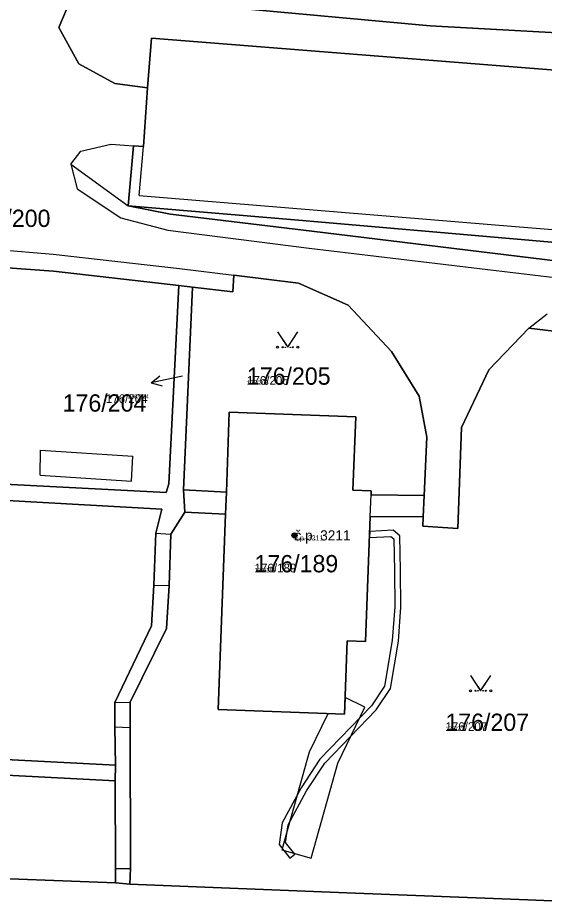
# Model space of a CAD drawing. Extents: x -759873 to -758487, y -975024 to -973516.
# Drawn here: x -759623.1 to -759571.4, y -974856.7 to -974770.4 of the extents above; entities that cross this region are included whole.
import ezdxf

# ---------------------------------------------------------------- set-up
doc = ezdxf.new("R2010")
doc.units = 0
for name, color, linetype in [('KAT_02_hranice parcel', 7, 'Continuous'), ('KAT_03_1000_st čísla parcelní', 7, 'Continuous'), ('KAT_03_1000_čísla parcelní', 7, 'Continuous'), ('KAT_03_1000_čísla popisná', 7, 'Continuous'), ('KAT_03_250_st čísla parcelní', 7, 'Continuous'), ('KAT_03_250_čísla parcelní', 7, 'Continuous'), ('KAT_03_250_čísla popisná', 7, 'Continuous'), ('KAT_03_500_st čísla parcelní', 7, 'Continuous'), ('KAT_03_500_čísla parcelní', 7, 'Continuous'), ('KAT_03_500_čísla popisná', 7, 'Continuous'), ('KAT_04_vnitřní kresba', 7, 'Continuous'), ('KAT_05_1000_značky kultur', 7, 'Continuous'), ('KAT_05_250_značky kultur', 7, 'Continuous'), ('KAT_05_500_značky kultur', 7, 'Continuous'), ('KAT_07_1000_značky budov', 7, 'Continuous'), ('KAT_07_250_značky budov', 7, 'Continuous'), ('KAT_07_500_značky budov', 7, 'Continuous'), ('KAT_10_věcná břemena', 7, 'Continuous'), ('KAT_12_pomocná šipka', 7, 'Continuous'), ('KAT_14_plocha_budovy', 7, 'Continuous'), ('KAT_14_plocha_pozemek', 7, 'Continuous')]:
    doc.layers.add(name, color=color, linetype=linetype)

msp = doc.modelspace()

# ---------------------------------------------------------------- linework, layer by layer
at = {"layer": 'KAT_02_hranice parcel'}
for p, q in [((-759607.29, -974796.68), (-759605.95, -974796.84)), ((-759606.81, -974816.78), (-759605.95, -974796.84)), ((-759606.81, -974816.78), (-759606.69, -974818.97)), ((-759583.29, -974819.43), (-759583.18, -974817.31)), ((-759613.54, -974845.35), (-759613.5, -974843.8)), ((-759612.08, -974855.52), (-759613.51, -974855.38))]:
    msp.add_line(p, q, dxfattribs=at)
for points in [[(-759493.33, -974775.87), (-759498.32, -974775.83), (-759582.59, -974771.17), (-759622.27, -974767.52)], [(-759610.35, -974777.27), (-759613.56, -974776.84), (-759617.11, -974774.92), (-759619.06, -974771.36), (-759617.87, -974768.52), (-759622.27, -974767.52)], [(-759500.61, -974785.93), (-759500.3, -974781.07), (-759541.75, -974777.79), (-759572.8, -974775.33), (-759609.95, -974772.38), (-759610.35, -974777.27)], [(-759612.26, -974788.87), (-759611.74, -974782.97), (-759610.74, -974783.04), (-759610.35, -974777.27)], [(-759506.34, -974821.05), (-759506.33, -974817.78), (-759508.64, -974810.72), (-759514.71, -974803.91), (-759522.15, -974800.74), (-759530.11, -974799.18), (-759550.41, -974796.65), (-759570.02, -974794.3), (-759594.2, -974791.34), (-759608.08, -974789.67), (-759612.26, -974788.87)], [(-759612.26, -974788.87), (-759595.53, -974790.27), (-759574.41, -974792.12), (-759557.24, -974793.62), (-759539.2, -974795.18), (-759522.98, -974796.45), (-759500.22, -974797.96), (-759499.79, -974792.57), (-759501.06, -974792.24)], [(-759658.47, -974814.76), (-759658.14, -974807.03), (-759656.32, -974802.8), (-759652.94, -974797.71), (-759651.6, -974796.18), (-759650.1, -974795.21), (-759637.14, -974794.79), (-759628.18, -974794.67), (-759619.59, -974795.29), (-759607.29, -974796.68)], [(-759605.95, -974796.84), (-759601.97, -974797.3), (-759601.86, -974795.66), (-759595.52, -974796.45), (-759590.65, -974798.61), (-759586.4, -974803.18), (-759583.69, -974807.58), (-759582.91, -974811.58), (-759583.18, -974817.31)], [(-759635.19, -974815.65), (-759608.52, -974817.04), (-759608.26, -974816.17), (-759607.29, -974796.68)], [(-759583.29, -974819.43), (-759583.32, -974820.34), (-759579.88, -974820.55), (-759579.53, -974810.64), (-759576.85, -974804.99), (-759572.9, -974800.89), (-759557.33, -974802.75)], [(-759583.18, -974817.31), (-759588.4, -974817.27), (-759588.39, -974816.87), (-759590.2, -974816.8), (-759589.9, -974809.61), (-759602.32, -974809.12), (-759602.61, -974817), (-759606.81, -974816.78)], [(-759613.5, -974843.8), (-759613.55, -974840.04), (-759613.55, -974837.66), (-759609.96, -974830.14), (-759609.73, -974826.13), (-759609.54, -974821.02), (-759608.96, -974818.66), (-759635.26, -974817.18)], [(-759613.54, -974845.35), (-759644.32, -974843.75), (-759652.64, -974841.53), (-759658.71, -974839.08), (-759660.02, -974837.93), (-759660.42, -974836.39), (-759660.21, -974820.73), (-759660.31, -974819.06)], [(-759658.82, -974818.97), (-759658.71, -974820.63), (-759658.89, -974836.21), (-759657.92, -974837.78), (-759652.31, -974840.06), (-759644, -974842.25), (-759613.5, -974843.8)], [(-759612.08, -974855.52), (-759612.01, -974853.96), (-759612.06, -974840.11), (-759612.04, -974837.62), (-759608.5, -974830.39), (-759608.23, -974826.18), (-759608.06, -974821.13), (-759606.69, -974818.97)], [(-759606.69, -974818.97), (-759602.69, -974819.15), (-759603.4, -974838.36), (-759591.01, -974838.82), (-759590.75, -974831.6), (-759588.94, -974831.66), (-759588.48, -974819.39), (-759583.29, -974819.43)], [(-759613.51, -974855.38), (-759613.51, -974853.96), (-759613.54, -974845.35)], [(-759613.51, -974855.38), (-759629.09, -974854.78), (-759656.08, -974853.68), (-759679.76, -974852.8), (-759694.68, -974852.23), (-759697.34, -974852.13), (-759701.47, -974851.98), (-759711.23, -974851.62), (-759720.36, -974851.23)], [(-759558.86, -974857.64), (-759572.99, -974857.06), (-759590.79, -974856.36), (-759612.08, -974855.52)]]:
    msp.add_lwpolyline(points, dxfattribs=at)
at = {"layer": 'KAT_03_1000_čísla popisná'}
msp.add_circle((-759595.92, -974821.24), 0.25, dxfattribs=at)
at = {"layer": 'KAT_03_250_čísla popisná'}
msp.add_circle((-759595.92, -974821.24), 0.0625, dxfattribs=at)
at = {"layer": 'KAT_03_500_čísla popisná'}
msp.add_circle((-759595.92, -974821.24), 0.125, dxfattribs=at)
at = {"layer": 'KAT_04_vnitřní kresba'}
for p, q in [((-759616.91, -974783.5), (-759613.96, -974782.81)), ((-759613.96, -974782.81), (-759611.74, -974782.97)), ((-759617.88, -974784.76), (-759616.91, -974783.5)), ((-759611.17, -974787.84), (-759610.74, -974783.04)), ((-759617.88, -974784.76), (-759617.26, -974787.2)), ((-759617.88, -974784.76), (-759612.26, -974788.87)), ((-759617.26, -974787.2), (-759612.96, -974790.03)), ((-759611.17, -974787.84), (-759574.2, -974790.9)), ((-759612.96, -974790.03), (-759608.35, -974791.26)), ((-759608.35, -974791.26), (-759594.47, -974793.01)), ((-759574.2, -974790.9), (-759539.16, -974793.84)), ((-759627.97, -974792.94), (-759619.61, -974793.6)), ((-759594.47, -974793.01), (-759570.36, -974795.92)), ((-759619.61, -974793.6), (-759607.21, -974795.01)), ((-759607.21, -974795.01), (-759601.86, -974795.66)), ((-759572.9, -974800.89), (-759571.1, -974799.47)), ((-759620.9, -974815.34), (-759620.87, -974812.88)), ((-759620.87, -974812.88), (-759611.78, -974813.47)), ((-759611.94, -974815.93), (-759611.78, -974813.47)), ((-759620.9, -974815.34), (-759611.94, -974815.93)), ((-759602.69, -974819.15), (-759602.61, -974817)), ((-759588.48, -974819.39), (-759588.4, -974817.27)), ((-759609.54, -974821.02), (-759608.06, -974821.13)), ((-759609.73, -974826.13), (-759608.23, -974826.18)), ((-759613.55, -974837.66), (-759612.04, -974837.62)), ((-759613.55, -974840.04), (-759612.06, -974840.11)), ((-759613.51, -974853.96), (-759612.01, -974853.96))]:
    msp.add_line(p, q, dxfattribs=at)
at = {"layer": 'KAT_05_1000_značky kultur'}
for points in [[(-759597.58, -974801.259), (-759596.58, -974802.76), (-759595.58, -974801.259)], [(-759578.64, -974835.009), (-759577.64, -974836.51), (-759576.64, -974835.009)]]:
    msp.add_lwpolyline(points, dxfattribs=at)
for centre in [(-759597.58, -974802.759), (-759595.58, -974802.759), (-759578.64, -974836.509), (-759576.64, -974836.509)]:
    msp.add_circle(centre, 0.1, dxfattribs=at)
at = {"layer": 'KAT_05_250_značky kultur'}
for points in [[(-759596.83, -974802.385), (-759596.58, -974802.76), (-759596.33, -974802.385)], [(-759577.89, -974836.135), (-759577.64, -974836.51), (-759577.39, -974836.135)]]:
    msp.add_lwpolyline(points, dxfattribs=at)
for centre in [(-759596.83, -974802.76), (-759596.33, -974802.76), (-759577.89, -974836.51), (-759577.39, -974836.51)]:
    msp.add_circle(centre, 0.025, dxfattribs=at)
at = {"layer": 'KAT_05_500_značky kultur'}
for points in [[(-759597.08, -974802.01), (-759596.58, -974802.76), (-759596.08, -974802.01)], [(-759578.14, -974835.76), (-759577.64, -974836.51), (-759577.14, -974835.76)]]:
    msp.add_lwpolyline(points, dxfattribs=at)
for centre in [(-759597.08, -974802.76), (-759596.08, -974802.76), (-759578.14, -974836.51), (-759577.14, -974836.51)]:
    msp.add_circle(centre, 0.05, dxfattribs=at)
at = {"layer": 'KAT_07_1000_značky budov'}
msp.add_circle((-759595.927, -974821.239), 0.175, dxfattribs=at)
at = {"layer": 'KAT_07_250_značky budov'}
msp.add_circle((-759595.922, -974821.24), 0.0437, dxfattribs=at)
at = {"layer": 'KAT_07_500_značky budov'}
msp.add_circle((-759595.923, -974821.24), 0.0875, dxfattribs=at)
at = {"layer": 'KAT_10_věcná břemena'}
for points in [[(-759588.53, -974820.85), (-759588.56, -974821.45), (-759586.45, -974821.34), (-759586.17, -974821.58), (-759586.11, -974824.69), (-759586.06, -974828.26), (-759586.32, -974831.57), (-759587.08, -974836.06), (-759588.35, -974837.99), (-759593.43, -974843.24), (-759595.27, -974846.04), (-759597.13, -974849.48), (-759597.42, -974851.6), (-759596.36, -974852.94), (-759595.89, -974852.57), (-759596.8, -974851.42), (-759596.55, -974849.68), (-759594.75, -974846.34), (-759592.95, -974843.62), (-759587.89, -974838.37), (-759586.5, -974836.28), (-759585.72, -974831.65), (-759585.46, -974828.28), (-759585.51, -974824.69), (-759585.57, -974821.3), (-759586.23, -974820.72)], [(-759590.95, -974837.18), (-759591.01, -974838.82), (-759592.65, -974838.76), (-759594.47, -974842.55), (-759597.16, -974852.14), (-759594.27, -974852.95), (-759591.65, -974843.61), (-759589.01, -974838.12)]]:
    msp.add_lwpolyline(points, close=True, dxfattribs=at)
at = {"layer": 'KAT_12_pomocná šipka'}
for p, q in [((-759610.005, -974806.264), (-759609.13, -974805.566)), ((-759607.07, -974805.64), (-759610.005, -974806.264)), ((-759606.91, -974805.61), (-759607.07, -974805.64)), ((-759610.005, -974806.264), (-759608.922, -974806.546))]:
    msp.add_line(p, q, dxfattribs=at)
at = {"layer": 'KAT_14_plocha_budovy'}
msp.add_lwpolyline([(-759603.4, -974838.36), (-759591.01, -974838.82), (-759590.75, -974831.6), (-759588.94, -974831.66), (-759588.48, -974819.39), (-759588.4, -974817.27), (-759588.39, -974816.87), (-759590.2, -974816.8), (-759589.9, -974809.61), (-759602.32, -974809.12), (-759602.61, -974817), (-759602.69, -974819.15)], close=True, dxfattribs=at)
at = {"layer": 'KAT_14_plocha_pozemek'}
for points in [[(-759622.27, -974767.52), (-759582.59, -974771.17), (-759498.32, -974775.83), (-759493.33, -974775.87), (-759476.62, -974776.02), (-759473.09, -974776.05), (-759471.04, -974776.07), (-759459.82, -974776.57), (-759452, -974776.85)], [(-759570.02, -974794.3), (-759594.2, -974791.34), (-759608.08, -974789.67), (-759612.26, -974788.87), (-759611.74, -974782.97), (-759610.74, -974783.04), (-759610.35, -974777.27), (-759613.56, -974776.84), (-759617.11, -974774.92), (-759619.06, -974771.36), (-759617.87, -974768.52)], [(-759557.24, -974793.62), (-759574.41, -974792.12), (-759595.53, -974790.27), (-759612.26, -974788.87), (-759608.08, -974789.67), (-759594.2, -974791.34), (-759570.02, -974794.3)], [(-759628.18, -974794.67), (-759619.59, -974795.29), (-759607.29, -974796.68), (-759605.95, -974796.84), (-759601.97, -974797.3), (-759601.86, -974795.66), (-759595.52, -974796.45), (-759590.65, -974798.61), (-759586.4, -974803.18), (-759583.69, -974807.58), (-759582.91, -974811.58), (-759583.18, -974817.31), (-759583.29, -974819.43), (-759583.32, -974820.34), (-759579.88, -974820.55), (-759579.53, -974810.64), (-759576.85, -974804.99), (-759572.9, -974800.89), (-759557.33, -974802.75)], [(-759635.26, -974817.18), (-759608.96, -974818.66), (-759609.54, -974821.02), (-759609.73, -974826.13), (-759609.96, -974830.14), (-759613.55, -974837.66), (-759613.55, -974840.04), (-759613.5, -974843.8), (-759613.54, -974845.35), (-759613.51, -974853.96), (-759613.51, -974855.38), (-759612.08, -974855.52), (-759612.01, -974853.96), (-759612.06, -974840.11), (-759612.04, -974837.62), (-759608.5, -974830.39), (-759608.23, -974826.18), (-759608.06, -974821.13), (-759606.69, -974818.97), (-759606.81, -974816.78), (-759605.95, -974796.84), (-759607.29, -974796.68), (-759608.26, -974816.17), (-759608.52, -974817.04), (-759635.19, -974815.65)], [(-759557.33, -974802.75), (-759572.9, -974800.89), (-759576.85, -974804.99), (-759579.53, -974810.64), (-759579.88, -974820.55), (-759583.32, -974820.34), (-759583.29, -974819.43), (-759588.48, -974819.39), (-759588.94, -974831.66), (-759590.75, -974831.6), (-759591.01, -974838.82), (-759603.4, -974838.36), (-759602.69, -974819.15), (-759606.69, -974818.97), (-759608.06, -974821.13), (-759608.23, -974826.18), (-759608.5, -974830.39), (-759612.04, -974837.62), (-759612.06, -974840.11), (-759612.01, -974853.96), (-759612.08, -974855.52), (-759590.79, -974856.36), (-759572.99, -974857.06), (-759558.86, -974857.64)], [(-759679.76, -974852.8), (-759656.08, -974853.68), (-759629.09, -974854.78), (-759613.51, -974855.38), (-759613.51, -974853.96), (-759613.54, -974845.35), (-759644.32, -974843.75), (-759652.64, -974841.53), (-759658.71, -974839.08), (-759660.02, -974837.93), (-759660.42, -974836.39), (-759660.21, -974820.73), (-759660.31, -974819.06), (-759663.72, -974818.93)], [(-759558.86, -974857.64), (-759572.99, -974857.06), (-759590.79, -974856.36), (-759612.08, -974855.52), (-759613.51, -974855.38), (-759629.09, -974854.78), (-759656.08, -974853.68), (-759679.76, -974852.8)]]:
    msp.add_lwpolyline(points, dxfattribs=at)
for points in [[(-759493.33, -974775.87), (-759498.32, -974775.83), (-759582.59, -974771.17), (-759622.27, -974767.52), (-759617.87, -974768.52), (-759619.06, -974771.36), (-759617.11, -974774.92), (-759613.56, -974776.84), (-759610.35, -974777.27), (-759609.95, -974772.38), (-759572.8, -974775.33), (-759541.75, -974777.79), (-759500.3, -974781.07), (-759500.61, -974785.93), (-759495.44, -974785.77), (-759491.14, -974783.19), (-759489.31, -974781.1), (-759489.41, -974779.52), (-759492.24, -974776.63)], [(-759500.61, -974785.93), (-759500.3, -974781.07), (-759541.75, -974777.79), (-759572.8, -974775.33), (-759609.95, -974772.38), (-759610.35, -974777.27), (-759610.74, -974783.04), (-759611.74, -974782.97), (-759612.26, -974788.87), (-759595.53, -974790.27), (-759574.41, -974792.12), (-759557.24, -974793.62), (-759539.2, -974795.18), (-759522.98, -974796.45), (-759500.22, -974797.96), (-759499.79, -974792.57), (-759501.06, -974792.24)], [(-759607.29, -974796.68), (-759619.59, -974795.29), (-759628.18, -974794.67), (-759637.14, -974794.79), (-759650.1, -974795.21), (-759651.6, -974796.18), (-759652.94, -974797.71), (-759656.32, -974802.8), (-759658.14, -974807.03), (-759658.47, -974814.76), (-759652.55, -974815.16), (-759652.25, -974807.29), (-759639.83, -974807.73), (-759640.15, -974814.97), (-759638.35, -974815.04), (-759638.36, -974815.44), (-759635.19, -974815.65), (-759608.52, -974817.04), (-759608.26, -974816.17)], [(-759606.81, -974816.78), (-759602.61, -974817), (-759602.32, -974809.12), (-759589.9, -974809.61), (-759590.2, -974816.8), (-759588.39, -974816.87), (-759588.4, -974817.27), (-759583.18, -974817.31), (-759582.91, -974811.58), (-759583.69, -974807.58), (-759586.4, -974803.18), (-759590.65, -974798.61), (-759595.52, -974796.45), (-759601.86, -974795.66), (-759601.97, -974797.3), (-759605.95, -974796.84)], [(-759583.18, -974817.31), (-759588.4, -974817.27), (-759588.39, -974816.87), (-759590.2, -974816.8), (-759589.9, -974809.61), (-759602.32, -974809.12), (-759602.61, -974817), (-759606.81, -974816.78), (-759606.69, -974818.97), (-759602.69, -974819.15), (-759603.4, -974838.36), (-759591.01, -974838.82), (-759590.75, -974831.6), (-759588.94, -974831.66), (-759588.48, -974819.39), (-759583.29, -974819.43)], [(-759652.31, -974840.06), (-759644, -974842.25), (-759613.5, -974843.8), (-759613.55, -974840.04), (-759613.55, -974837.66), (-759609.96, -974830.14), (-759609.73, -974826.13), (-759609.54, -974821.02), (-759608.96, -974818.66), (-759635.26, -974817.18), (-759638.44, -974817.55), (-759638.9, -974829.81), (-759640.71, -974829.74), (-759640.98, -974836.96), (-759653.35, -974836.49), (-759652.63, -974817.31), (-759658.58, -974816.89), (-759658.82, -974818.97), (-759658.71, -974820.63), (-759658.89, -974836.21), (-759657.92, -974837.78)], [(-759613.5, -974843.8), (-759644, -974842.25), (-759652.31, -974840.06), (-759657.92, -974837.78), (-759658.89, -974836.21), (-759658.71, -974820.63), (-759658.82, -974818.97), (-759660.31, -974819.06), (-759660.21, -974820.73), (-759660.42, -974836.39), (-759660.02, -974837.93), (-759658.71, -974839.08), (-759652.64, -974841.53), (-759644.32, -974843.75), (-759613.54, -974845.35)]]:
    msp.add_lwpolyline(points, close=True, dxfattribs=at)

# ---------------------------------------------------------------- texts
at = {"layer": 'KAT_03_1000_st čísla parcelní'}
msp.add_text('176/189', height=1.7, dxfattribs=at).set_placement((-759599.84, -974824.87))
at = {"layer": 'KAT_03_1000_čísla parcelní'}
for s, p in [('176/200', (-759628.1, -974790.94)), ('176/205', (-759600.59, -974806.44)), ('176/204', (-759618.686, -974809.083)), ('176/207', (-759581.1, -974840.45))]:
    msp.add_text(s, height=1.7, dxfattribs=at).set_placement(p)
at = {"layer": 'KAT_03_1000_čísla popisná'}
msp.add_text('č.p. 3211', height=1, dxfattribs=at).set_placement((-759595.92, -974821.74))
at = {"layer": 'KAT_03_250_st čísla parcelní'}
msp.add_text('176/189', height=0.425, dxfattribs=at).set_placement((-759599.84, -974824.87))
at = {"layer": 'KAT_03_250_čísla parcelní'}
for s, p in [('176/205', (-759600.59, -974806.44)), ('176/204', (-759612.336, -974807.808)), ('176/207', (-759581.1, -974840.45))]:
    msp.add_text(s, height=0.425, dxfattribs=at).set_placement(p)
at = {"layer": 'KAT_03_250_čísla popisná'}
msp.add_text('č.p. 3211', height=0.25, dxfattribs=at).set_placement((-759595.92, -974821.74))
at = {"layer": 'KAT_03_500_st čísla parcelní'}
msp.add_text('176/189', height=0.85, dxfattribs=at).set_placement((-759599.84, -974824.87))
at = {"layer": 'KAT_03_500_čísla parcelní'}
for s, p in [('176/205', (-759600.59, -974806.44)), ('176/204', (-759614.453, -974808.233)), ('176/207', (-759581.1, -974840.45))]:
    msp.add_text(s, height=0.85, dxfattribs=at).set_placement(p)
at = {"layer": 'KAT_03_500_čísla popisná'}
msp.add_text('č.p. 3211', height=0.5, dxfattribs=at).set_placement((-759595.92, -974821.74))

doc.saveas('drawing.dxf')
